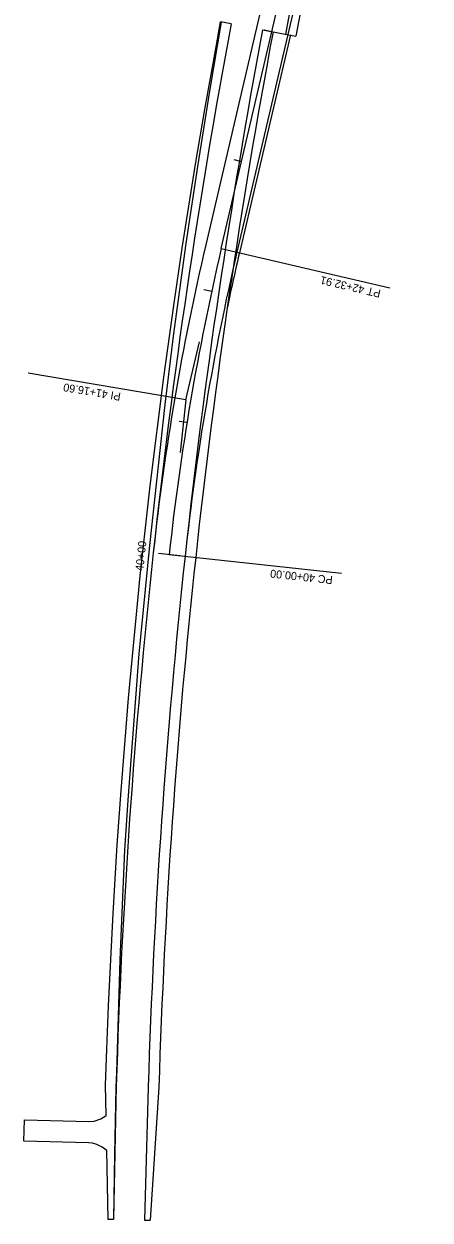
# Model space of a CAD drawing. Extents: x 1445610 to 1446352, y 2042797 to 2056486.
# Drawn here: x 1445610 to 1445914, y 2053367 to 2054264 of the extents above; entities that cross this region are included whole.
import ezdxf

# ---------------------------------------------------------------- set-up
doc = ezdxf.new("R2010")
doc.units = 0
for name, color, linetype in [('20', 7, 'Continuous'), ('R_Horz Alg', 7, 'Continuous'), ('R_Horz Alg Annot_Detour', 7, 'Continuous'), ('R_Horz Alg Stationing_Detour', 7, 'Continuous'), ('R_Proposed Road', 7, 'Continuous')]:
    doc.layers.add(name, color=color, linetype=linetype)

msp = doc.modelspace()

# ---------------------------------------------------------------- linework, layer by layer
at = {"layer": '20'}
msp.add_lwpolyline([(1445757.58, 2054265.12), (1445748.87, 2054213.35), (1445739.85, 2054156.89), (1445731.16, 2054098.98), (1445721.68, 2054029.5), (1445715.4, 2053978.42), (1445703.83, 2053872.49), (1445695.82, 2053791.4), (1445687.57, 2053681.64), (1445685.14, 2053644.13), (1445681.57, 2053561.9), (1445678.98, 2053477.77), (1445678.65, 2053466.19), (1445677.65, 2053416.08), (1445676.84, 2053367.1), (1445672.74, 2053367.15), (1445671.8, 2053418.83), (1445668.42, 2053421.56), (1445664.36, 2053423.56), (1445660.99, 2053424.44), (1445658.1, 2053424.72), (1445609.63, 2053425.9), (1445610, 2053441.89), (1445658.29, 2053440.72), (1445662.36, 2053441.04), (1445667.37, 2053442.66), (1445671.32, 2053445.14), (1445670.93, 2053468.01), (1445671.84, 2053495.04), (1445673.12, 2053527.41), (1445676.52, 2053596.62), (1445679.64, 2053648.08), (1445682.49, 2053688.99), (1445688.02, 2053758.03), (1445696.83, 2053849.97), (1445704.34, 2053917.44), (1445714.58, 2053998.85), (1445722.06, 2054052.61), (1445728.43, 2054095.53), (1445738.47, 2054158.62), (1445745.43, 2054199.66), (1445753.77, 2054246.47), (1445757.23, 2054265.18)], dxfattribs=at)
at = {"layer": 'R_Horz Alg'}
msp.add_line((1445757.73, 2054095.33), (1445849.12, 2054486.09), dxfattribs=at)
msp.add_arc((1447617.41, 2053660.4), 1909.86, 166.83661, 173.8239, dxfattribs=at)
at = {"layer": 'R_Horz Alg Annot_Detour'}
for q in [(1445741.36, 2054025.32), (1445726.9, 2053942.25)]:
    msp.add_line((1445731.18, 2053981.8), q, dxfattribs=at)
for points in [[(1445757.73, 2054095.33), (1445884.32, 2054065.73)], [(1445731.18, 2053981.8), (1445612.89, 2054001.95)], [(1445718.64, 2053865.88), (1445847.88, 2053851.89)]]:
    msp.add_lwpolyline(points, dxfattribs=at)
at = {"layer": 'R_Horz Alg Stationing_Detour'}
for points in [[(1445789.94, 2054259.4), (1445795.78, 2054258.03)], [(1445767.17, 2054162.03), (1445773.01, 2054160.66)], [(1445744.65, 2054064.49), (1445750.52, 2054063.23)], [(1445726.07, 2053965.93), (1445731.99, 2053964.97)], [(1445710.68, 2053866.74), (1445726.59, 2053865.02)]]:
    msp.add_lwpolyline(points, dxfattribs=at)
at = {"layer": 'R_Proposed Road'}
for p, q in [((1445837.44, 2054488.82), (1445746.05, 2054098.07)), ((1445860.81, 2054483.36), (1445769.42, 2054092.6)), ((1445765.09, 2054263.71), (1445757.23, 2054265.18)), ((1445788.69, 2054259.31), (1445813.75, 2054254.63)), ((1445809.55, 2054255.41), (1445771.37, 2054092.15)), ((1445678.91, 2053467.31), (1445676.84, 2053367.1)), ((1445702.9, 2053466.56), (1445700.07, 2053366.83)), ((1445710.9, 2053466.32), (1445704.36, 2053366.78)), ((1445700.07, 2053366.83), (1445704.36, 2053366.78))]:
    msp.add_line(p, q, dxfattribs=at)
for centre, radius, start, end in [((1450897.11, 2053305.5), 5179.21, 164.16667, 169.4239), ((1450897.11, 2053305.5), 5171.21, 166.12925, 169.4239), ((1450897.11, 2053305.5), 5220.71, 169.4239, 178.2239), ((1450897.11, 2053305.5), 5196.71, 169.4239, 178.2239), ((1450897.11, 2053305.5), 5188.71, 169.4239, 178.2239), ((1447617.41, 2053660.4), 1921.86, 166.83661, 173.8239), ((1447617.41, 2053660.4), 1897.86, 166.83661, 173.8239), ((1447617.41, 2053660.4), 1895.86, 166.83661, 168.103)]:
    msp.add_arc(centre, radius, start, end, dxfattribs=at)

# ---------------------------------------------------------------- texts
at = {"layer": 'R_Horz Alg Annot_Detour'}
for s, rotation, p in [('PT 42+32.91', 166.83661, (1445877.79, 2054064.17)), ('PI 41+16.60', 170.33026, (1445682.66, 2053987.02)), ('PC 40+00.00', 173.8239, (1445841.59, 2053849.55))]:
    msp.add_text(s, height=6, rotation=rotation, dxfattribs=at).set_placement(p)
at = {"layer": 'R_Horz Alg Stationing_Detour'}
msp.add_text('40+00', height=6, rotation=83.8239, dxfattribs=at).set_placement((1445699.16, 2053853.25))

doc.saveas('drawing.dxf')
